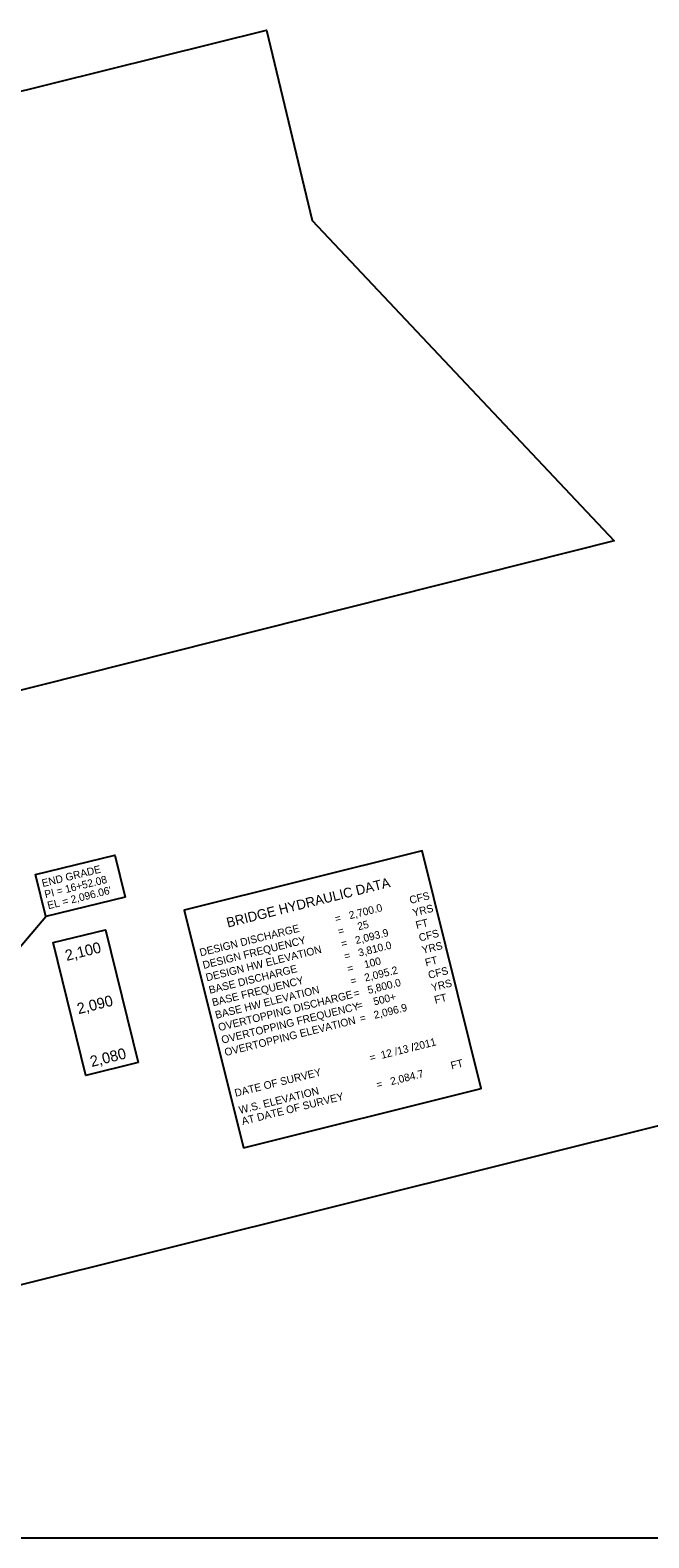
# Model space of a CAD drawing. Extents: x 1030663 to 1033857, y 654635 to 657099.
# Drawn here: x 1031692 to 1032261, y 655714 to 657099 of the extents above; entities that cross this region are included whole.
import ezdxf

# ---------------------------------------------------------------- set-up
doc = ezdxf.new("R2010")
doc.units = 0
for name, color, linetype in [('Exist DTM Spot Elevation Leader', 7, 'Continuous'), ('Exist Vertical Profile Vertical Axis Label', 7, 'Continuous'), ('Prop Grid Mask', 7, 'Continuous'), ('Prop Vertical Profile Grade Label', 7, 'Continuous'), ('Prop VPI Label', 7, 'Continuous'), ('Sheet Layout Plan Border', 7, 'Continuous')]:
    doc.layers.add(name, color=color, linetype=linetype)

msp = doc.modelspace()

# ---------------------------------------------------------------- linework, layer by layer
at = {"layer": 'Prop Grid Mask'}
for points in [[(1031779.7, 656302.9), (1031706.6, 656284.9), (1031697.1, 656323.5), (1031770.2, 656341.5)], [(1031888.4, 656072.6), (1032106.7, 656127), (1032052.3, 656345.3), (1031833.9, 656290.9)], [(1031791.6, 656150.8), (1031743.4, 656138.9), (1031713.3, 656261), (1031761.6, 656272.8)]]:
    msp.add_lwpolyline(points, close=True, dxfattribs=at)
at = {"layer": 'Prop Vertical Profile Grade Label'}
for p, q in [((1031629.2, 656193.6), (1031706.6, 656284.9)), ((1030750.5, 655714.1), (1032384, 656121.4)), ((1030750.5, 655714.1), (1032564.7, 655714.1))]:
    msp.add_line(p, q, dxfattribs=at)
at = {"layer": 'Sheet Layout Plan Border'}
msp.add_lwpolyline([(1030815.4, 656273.5), (1030662.8, 656790.2), (1030975.9, 656867.4), (1031909.3, 657099.3), (1031951.3, 656924.6), (1032228.7, 656630.1), (1031213.2, 656374.4)], close=True, dxfattribs=at)

# ---------------------------------------------------------------- texts
at = {"layer": 'Exist DTM Spot Elevation Leader'}
for s, height, p in [('BRIDGE HYDRAULIC DATA', 9, (1031873.9, 656274.8)), ('CFS', 7, (1032041.7, 656296.5)), ('=   2,700.0', 7, (1031973.2, 656279.3)), ('YRS', 7, (1032044.6, 656284.9)), ('DESIGN DISCHARGE', 7, (1031848.9, 656248.3)), ('=     25', 7, (1031976, 656267.8)), ('FT', 7, (1032047.4, 656273.5)), ('DESIGN FREQUENCY', 7, (1031851.7, 656236.8)), ('=   2,093.9', 7, (1031978.9, 656256.4)), ('CFS', 7, (1032050.3, 656262)), ('DESIGN HW ELEVATION', 7, (1031854.6, 656225.4)), ('=   3,810.0', 7, (1031981.7, 656244.9)), ('YRS', 7, (1032053.1, 656250.6)), ('BASE DISCHARGE', 7, (1031857.4, 656213.9)), ('=    100', 7, (1031984.6, 656233.5)), ('=   2,095.2', 7, (1031987.4, 656222)), ('FT', 7, (1032056, 656239.1)), ('CFS', 7, (1032058.8, 656227.7)), ('BASE FREQUENCY', 7, (1031860.3, 656202.5)), ('=   5,800.0', 7, (1031990.3, 656210.6)), ('YRS', 7, (1032061.7, 656216.2)), ('BASE HW ELEVATION', 7, (1031863.2, 656191)), ('OVERTOPPING DISCHARGE', 7, (1031866, 656179.6)), ('=    500+', 7, (1031993.1, 656199.4)), ('FT', 7, (1032064.5, 656204.8)), ('OVERTOPPING FREQUENCY', 7, (1031868.9, 656168.1)), ('=   2,096.9', 7, (1031996, 656187.7)), ('OVERTOPPING ELEVATION', 7, (1031871.7, 656156.7)), ('=  12 /13 /2011', 7, (1032005, 656151.6)), ('FT', 7, (1032079.6, 656144.5)), ('DATE OF SURVEY', 7, (1031881, 656119.3)), ('=   2,084.7', 7, (1032011.2, 656126.8)), ('W.S. ELEVATION', 7, (1031885, 656103.6)), ('AT DATE OF SURVEY', 7, (1031887.5, 656093.4))]:
    msp.add_text(s, height=height, rotation=14, dxfattribs=at).set_placement(p)
at = {"layer": 'Exist Vertical Profile Vertical Axis Label'}
for s, p in [('2,100', (1031725.8, 656244.1)), ('2,090', (1031736.7, 656195.2)), ('2,080', (1031748.8, 656146.7))]:
    msp.add_text(s, height=10, rotation=14, dxfattribs=at).set_placement(p)
at = {"layer": 'Prop VPI Label'}
for s, p in [('END GRADE', (1031703.9, 656312)), ('PI = 16+52.08', (1031706.4, 656301.8)), ("EL = 2,096.06'", (1031709, 656291.6))]:
    msp.add_text(s, height=7, rotation=14, dxfattribs=at).set_placement(p)

doc.saveas('drawing.dxf')
